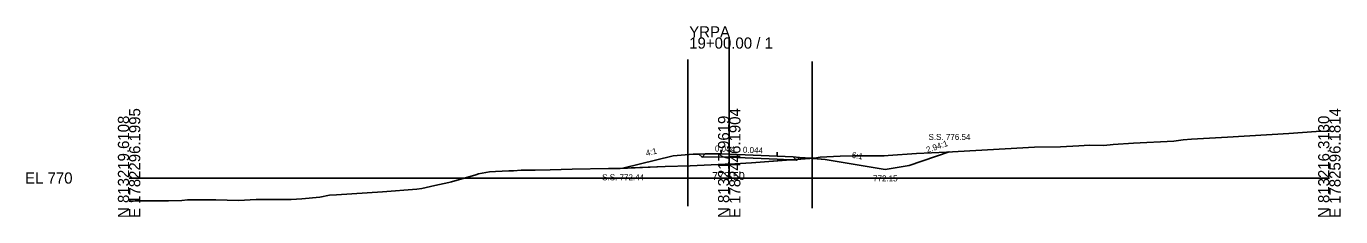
# Model space of a CAD drawing. Extents: x -26 to 2603, y -14 to 9545.
# Drawn here: x -25.7 to 302.8, y 8990.3 to 9038 of the extents above; entities that cross this region are included whole.
import ezdxf

# ---------------------------------------------------------------- set-up
doc = ezdxf.new("R2010")
doc.units = 0
for name, color, linetype in [('Exist Cross Section Cell', 7, 'Continuous'), ('Exist XS Center Line Elevation Label', 7, 'Continuous'), ('Exist XS Ground Line', 7, 'Continuous'), ('Prop XS Ditch Slope Text', 7, 'Continuous'), ('Prop XS Ditch Standard Text', 7, 'Continuous'), ('Prop XS Dump Level', 7, 'Continuous'), ('Prop XS Earthwork Shape', 7, 'Continuous'), ('Prop XS EOT Tick Mark', 7, 'Continuous'), ('Prop XS Exc Vertical Line 1', 7, 'Continuous'), ('Prop XS Exc Vertical Line 2', 7, 'Continuous'), ('Prop XS Finish Grade', 7, 'Continuous'), ('Prop XS Finish Grade Earthwork', 7, 'Continuous'), ('Prop XS Finish Grade Paved Shoulder', 7, 'Continuous'), ('Prop XS Finish Grade Pavement', 7, 'Continuous'), ('Prop XS Hydro Fill Slope Data', 7, 'Continuous'), ('Prop XS Pvmt Edge Slope', 7, 'Continuous'), ('Prop XS SE Text', 7, 'Continuous'), ('Prop XS Side Slope Text', 7, 'Continuous'), ('Prop XS SS Elevation Text', 7, 'Continuous'), ('Prop XS Subgrade Earthwork', 7, 'Continuous'), ('Scratch_Level_6', 7, 'Continuous')]:
    doc.layers.add(name, color=color, linetype=linetype)

msp = doc.modelspace()

# ---------------------------------------------------------------- linework, layer by layer
at = {"layer": 'Exist Cross Section Cell'}
for p, q in [((150, 9000), (150, 9035.19)), ((0, 9000), (150, 9000)), ((150, 9000), (300, 9000))]:
    msp.add_line(p, q, dxfattribs=at)
at = {"layer": 'Exist XS Ground Line'}
for p, q in [((296.67, 9011.65), (300, 9011.73)), ((243.65, 9008.15), (245.94, 9008.4)), ((245.94, 9008.4), (251.08, 9008.69)), ((251.08, 9008.69), (261.1, 9009.19)), ((261.1, 9009.19), (263.43, 9009.56)), ((263.43, 9009.56), (265.57, 9009.69)), ((265.57, 9009.69), (274.51, 9010.26)), ((274.51, 9010.26), (289.84, 9011.17)), ((289.84, 9011.17), (296.67, 9011.65)), ((171.31, 9004.99), (172.77, 9005.22)), ((172.77, 9005.22), (177.75, 9005.46)), ((177.75, 9005.46), (180.98, 9005.57)), ((180.98, 9005.57), (187.15, 9005.56)), ((187.15, 9005.56), (188.74, 9005.58)), ((188.74, 9005.58), (189.74, 9005.63)), ((189.74, 9005.63), (196.85, 9006.11)), ((196.85, 9006.11), (204.27, 9006.5)), ((204.27, 9006.5), (226.31, 9007.75)), ((226.31, 9007.75), (232.82, 9007.79)), ((232.82, 9007.79), (237.42, 9008.1)), ((237.42, 9008.1), (240.08, 9008.26)), ((240.08, 9008.26), (243.65, 9008.15)), ((96.07, 9001.76), (97.98, 9001.93)), ((97.98, 9001.93), (101.54, 9001.96)), ((101.54, 9001.96), (105.25, 9002.01)), ((105.25, 9002.01), (110.74, 9002.24)), ((110.74, 9002.24), (119.84, 9002.36)), ((119.84, 9002.36), (122.76, 9002.41)), ((122.76, 9002.41), (133.98, 9002.85)), ((133.98, 9002.85), (140.25, 9003.02)), ((140.25, 9003.02), (148.98, 9003.44)), ((148.98, 9003.44), (150, 9003.5)), ((150, 9003.5), (155.55, 9003.8)), ((155.55, 9003.8), (165.41, 9004.54)), ((165.41, 9004.54), (171.31, 9004.99)), ((76.43, 8998.13), (79.94, 8998.89)), ((79.94, 8998.89), (80.58, 8999.05)), ((80.58, 8999.05), (86.65, 9000.82)), ((86.65, 9000.82), (87.34, 9001.03)), ((87.34, 9001.03), (90.11, 9001.59)), ((90.11, 9001.59), (91.62, 9001.65)), ((91.62, 9001.65), (94.9, 9001.78)), ((94.9, 9001.78), (96.07, 9001.76)), ((47.69, 8995.21), (50.08, 8995.69)), ((50.08, 8995.69), (51.82, 8995.77)), ((51.82, 8995.77), (63.38, 8996.57)), ((63.38, 8996.57), (71.9, 8997.2)), ((71.9, 8997.2), (73.15, 8997.4)), ((73.15, 8997.4), (76.43, 8998.13)), ((0, 8994.21), (1.03, 8994.23)), ((1.03, 8994.23), (1.56, 8994.25)), ((1.56, 8994.25), (2.84, 8994.26)), ((2.84, 8994.26), (9.89, 8994.33)), ((9.89, 8994.33), (13.15, 8994.36)), ((13.15, 8994.36), (14.58, 8994.51)), ((14.58, 8994.51), (16.36, 8994.53)), ((16.36, 8994.53), (21.68, 8994.58)), ((21.68, 8994.58), (27.36, 8994.36)), ((27.36, 8994.36), (31.8, 8994.66)), ((31.8, 8994.66), (40.49, 8994.66)), ((40.49, 8994.66), (43.18, 8994.78)), ((43.18, 8994.78), (47.69, 8995.21))]:
    msp.add_line(p, q, dxfattribs=at)
at = {"layer": 'Prop XS Dump Level'}
for p, q in [((148, 9006.09), (150, 9006)), ((150, 9006), (162, 9005.47))]:
    msp.add_line(p, q, dxfattribs=at)
at = {"layer": 'Prop XS Earthwork Shape'}
for points in [[(161.96, 9004.68), (165.25, 9004.53), (155.55, 9003.8), (150, 9003.5), (148.98, 9003.44), (140.25, 9003.02), (133.98, 9002.85), (123.43, 9002.44), (136, 9005.58), (141, 9005.98), (142.42, 9006), (143.2, 9005.22), (147.99, 9005.3), (149.96, 9005.21)], [(167.04, 9004.67), (170.49, 9004.93), (169, 9005.05), (167.54, 9005.17)], [(188.74, 9005.58), (189.74, 9005.63), (196.85, 9006.11), (204.27, 9006.5), (205, 9006.54), (195, 9003.15), (189, 9002.15), (174, 9004.65), (170.49, 9004.93), (171.31, 9004.99), (172.77, 9005.22), (177.75, 9005.46), (180.98, 9005.57), (187.15, 9005.56)], [(165.25, 9004.53), (165.41, 9004.54), (167.04, 9004.67), (166.83, 9004.46)]]:
    msp.add_lwpolyline(points, close=True, dxfattribs=at)
at = {"layer": 'Prop XS EOT Tick Mark'}
for p, q in [((148, 9006.09), (148, 9007.09)), ((162, 9005.47), (162, 9006.47))]:
    msp.add_line(p, q, dxfattribs=at)
at = {"layer": 'Prop XS Exc Vertical Line 1'}
msp.add_line((139.66, 8992.95), (139.66, 9029.64), dxfattribs=at)
at = {"layer": 'Prop XS Exc Vertical Line 2'}
msp.add_line((170.72, 8992.47), (170.72, 9029.16), dxfattribs=at)
at = {"layer": 'Prop XS Finish Grade'}
for p, q in [((144, 9006.03), (142.42, 9006)), ((166, 9005.29), (167.54, 9005.17))]:
    msp.add_line(p, q, dxfattribs=at)
at = {"layer": 'Prop XS Finish Grade Earthwork'}
for p, q in [((136, 9005.58), (123.43, 9002.44)), ((136, 9005.58), (141, 9005.98)), ((141, 9005.98), (142.42, 9006)), ((167.54, 9005.17), (169, 9005.05)), ((195, 9003.15), (205, 9006.54)), ((169, 9005.05), (174, 9004.65)), ((174, 9004.65), (189, 9002.15)), ((189, 9002.15), (195, 9003.15))]:
    msp.add_line(p, q, dxfattribs=at)
at = {"layer": 'Prop XS Finish Grade Paved Shoulder'}
for p, q in [((148, 9006.09), (144, 9006.03)), ((162, 9005.47), (166, 9005.29))]:
    msp.add_line(p, q, dxfattribs=at)
at = {"layer": 'Prop XS Finish Grade Pavement'}
for p, q in [((148, 9006.09), (150, 9006)), ((150, 9006), (162, 9005.47))]:
    msp.add_line(p, q, dxfattribs=at)
at = {"layer": 'Prop XS Hydro Fill Slope Data'}
msp.add_line((136, 9005.58), (123.43, 9002.44), dxfattribs=at)
at = {"layer": 'Prop XS Pvmt Edge Slope'}
for p, q in [((144, 9006.03), (143.2, 9005.22)), ((166, 9005.29), (166.83, 9004.46))]:
    msp.add_line(p, q, dxfattribs=at)
at = {"layer": 'Prop XS Subgrade Earthwork'}
for p, q in [((143.2, 9005.22), (142.42, 9006)), ((147.99, 9005.3), (143.2, 9005.22)), ((147.99, 9005.3), (149.96, 9005.21)), ((149.96, 9005.21), (161.96, 9004.68)), ((166.83, 9004.46), (167.54, 9005.17)), ((161.96, 9004.68), (166.83, 9004.46))]:
    msp.add_line(p, q, dxfattribs=at)
at = {"layer": 'Scratch_Level_6'}
for points in [[(165.41, 9004.54), (167.04, 9004.67), (166.83, 9004.46), (165.25, 9004.53)], [(170.49, 9004.93), (170.72, 9004.91), (170.72, 9004.95)]]:
    msp.add_lwpolyline(points, close=True, dxfattribs=at)

# ---------------------------------------------------------------- texts
at = {"layer": 'Exist Cross Section Cell'}
for s, p in [('YRPA', (140, 9035.19)), ('19+00.00 / 1', (140, 9032.39)), ('EL 770', (-26, 8998.6))]:
    msp.add_text(s, height=2.8, dxfattribs=at).set_placement(p)
for s, p in [('N 813219.6108', (0, 8990)), ('E 1782296.1995', (2.8, 8990)), ('N 813217.9619', (150, 8990)), ('E 1782446.1904', (152.8, 8990)), ('N 813216.3130', (300, 8990)), ('E 1782596.1814', (302.8, 8990))]:
    msp.add_text(s, height=2.8, rotation=90, dxfattribs=at).set_placement(p)
at = {"layer": 'Exist XS Center Line Elevation Label'}
msp.add_text('773.50', height=2, dxfattribs=at).set_placement((145.71, 8999.5))
at = {"layer": 'Prop XS Ditch Slope Text'}
msp.add_text('6:1', height=1.5, rotation=350.5377, dxfattribs=at).set_placement((180.55, 9005.08))
at = {"layer": 'Prop XS Ditch Standard Text'}
msp.add_text('772.15', height=1.5, dxfattribs=at).set_placement((185.95, 8999.15))
at = {"layer": 'Prop XS Dump Level'}
for p in [(136, 9005.54), (174, 9004.61)]:
    msp.add_text('Case4', height=0.04, dxfattribs=at).set_placement(p)
at = {"layer": 'Prop XS SE Text'}
for p in [(146.39, 9006.66), (153.39, 9006.35)]:
    msp.add_text('0.044', height=1.5, rotation=357.4523, dxfattribs=at).set_placement(p)
at = {"layer": 'Prop XS Side Slope Text'}
for s, rotation, p in [('2.94:1', 18.7601, (199.52, 9006.27)), ('4:1', 14.0362, (129.35, 9005.46))]:
    msp.add_text(s, height=1.5, rotation=rotation, dxfattribs=at).set_placement(p)
at = {"layer": 'Prop XS SS Elevation Text'}
for s, p in [('S.S. 776.54', (199.81, 9009.54)), ('S.S. 772.44', (118.24, 8999.44))]:
    msp.add_text(s, height=1.5, dxfattribs=at).set_placement(p)

doc.saveas('drawing.dxf')
